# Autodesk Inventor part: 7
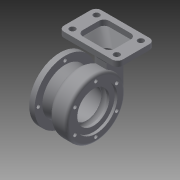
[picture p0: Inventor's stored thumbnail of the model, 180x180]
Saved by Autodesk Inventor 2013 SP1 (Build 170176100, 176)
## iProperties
Created: 2013-05
Part Number: 7
Material: Iron, Cast
Document SubType Name: Modeling
Designer: 50384
Density: 1 g/cm^3
Author: 50384
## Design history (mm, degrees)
sketch "Sketch1"
  geometry: L1 (0, 0)-(0, 40); L2 (0, 40)-(-5, 40); L3 (-5, 40)-(-5, 30); L4 (-5, 30)-(-10, 30); L5 (-10, 30)-(-10, 52); L6 (-10, 52)-(-22, 52); L7 (0, 40)-(0, 50); L8 (-5, 55)-(-22, 55); L9 (-37, 40)-(-37, 36.35); L10 (-57.45, 42.99)-(-37, 36.35); L11 (-57.45, 42.99)-(-57.45, 57.49); L12 (-57.45, 57.49)-(-67.45, 57.49); L13 (-67.45, 57.49)-(-67.45, 43.06); L14 (-17.435, 27.47)-(-63.445, 38.16); L15 (-17.435, 27.47)-(-18.622, 27.746); L16 (-17.895, 28.724)-(-34, 35.468); L17 (-34, 35.468)-(-34, 40); L18 (0, 0)-(-62.45, 0); A1 r 5 centre (-5, 50) between (0, 50) and (-5, 55); A2 r 5 centre (-62.45, 43.06) between (-67.45, 43.06) and (-63.445, 38.16); A3 r 1.219 centre (-18.622, 27.746) between (-17.435, 27.47) and (-17.895, 28.724); A4 r 12 centre (-22, 40) between (-22, 52) and (-34, 40); A5 r 15 centre (-22, 40) between (-22, 55) and (-37, 40); 1 further point
  constraints: 36 end point, 10 point on circle, 8 perpendicular, 5 centre point, 4 tangent, 3 parallel, 3 point on line, 2 coincident, 1 vertical
  dimensions: "d7" = 15 distance of L1.end point (0, 55); "d8" = 22 distance of point (0, 55) L8.end; "d9" = 5 radius of A1; "d12" = 3.65 distance of L9.start L9.end; "d15" = 14.5 distance of L10.start L11.end; "d16" = 10 distance of L11.end L12.end; "d17" = 14.43 distance of L13.end L12.end
revolve "Revolution1" sketch "Sketch1" stored, may be unused: angle "d22" = 90 deg
sketch "Sketch2" dims "d23" = 100
  geometry: C1 r 43.06 at (0, 0) reference; C2 r 3.4 at (0, 50); C3 r 3.4 at (-50, 0); C4 r 3.4 at (0, -50); C5 r 3.4 at (50, 0); 1 further point
  constraints: 4 centre point, 1 coincident, 1 vertical alignment, 11 other
  dimensions: "d24" = 6.8 diameter of C2; "d27" = 360 deg dimension on point (0, 0) C2.centre (derived)
extrude "Extrusion1" cut sketch "Sketch2" stored distance "d29" = 25.4; taper "d30" = 0 deg
workplane "Work Plane1"
sketch "Sketch3"
  geometry: L1 (5, 55)-(5, -55) reference; L2 (20, -75)-(75, -75); L3 (65, -75)-(-25, -75); L4 (-35, -65)-(-35, -15); L5 (-25, -5)-(65, -5); L6 (75, -15)-(75, -65); L7 (20, -5)-(20, -15); L8 (20, -15)-(0, -15); L9 (-35, -40)-(-10, -40); L10 (-10, -40)-(-10, -25); L11 (20, -65)-(0, -65); L12 (-10, -40)-(-10, -55); L13 (20, -15)-(40, -15); L14 (50, -40)-(50, -25); L15 (50, -40)-(50, -55); L16 (20, -65)-(40, -65); C1 r 5.5 at (61.46, -17.5); C2 r 5.5 at (61.46, -62.5); C3 r 5.5 at (-21.46, -17.5); C4 r 5.5 at (-21.46, -62.5); A1 r 10 centre (0, -25) between (0, -15) and (-10, -25); A2 r 10 centre (-25, -15) between (-25, -5) and (-35, -15); A3 r 10 centre (-25, -65) between (-35, -65) and (-25, -75); A4 r 10 centre (65, -65) between (65, -75) and (75, -65); A5 r 10 centre (65, -15) between (75, -15) and (65, -5); A6 r 10 centre (0, -55) between (-10, -55) and (0, -65); A7 r 10 centre (40, -25) between (50, -25) and (40, -15); A8 r 10 centre (40, -55) between (40, -65) and (50, -55); 4 further points
  constraints: 30 end point, 16 point on circle, 12 centre point, 11 symmetric about line, 10 tangent, 8 point on line, 4 equal radius, 4 parallel, 3 perpendicular, 2 midpoint, 1 horizontal, 3 other
  dimensions: "d35" = 55 distance of L2.start L2.end; "d36" = 110 distance of point (-35, -5) point (75, -5); "d37" = 70 distance of point (-35, -75) point (-35, -5); "d40" = 11 diameter of C1; "d41" = 10 distance of L7.start L7.end; "d42" = 25 distance of L9.start L9.end; "d43" = 10 radius of A1
extrude "Extrusion2" join sketch "Sketch3" distance "d44" = 10; taper "d45" = 0 deg
workplane "Work Plane2"
sketch "Sketch4"
  geometry: L1 (-10, -55)-(-10, -25) reference; L2 (0, -15)-(40, -15) reference; L3 (50, -25)-(50, -55) reference; L4 (40, -65)-(0, -65) reference; L5 (-35, -15)-(-35, -65) reference; L6 (-25, -75)-(65, -75) reference; L7 (75, -65)-(75, -15) reference; L8 (65, -5)-(-25, -5) reference; L9 (8, -40)-(8, -28); L10 (8, -28)-(20, -28); L11 (8, -52)-(20, -52); L12 (8, -40)-(8, -52); L13 (4, -28)-(4, -55); L14 (20, -24)-(4, -24); L15 (4, -24)-(4, -28); L16 (20, -56)-(4, -56); L17 (4, -56)-(4, -55); C1 r 5.5 at (-21.46, -62.5) reference; C2 r 5.5 at (61.46, -62.5) reference; C3 r 5.5 at (61.46, -17.5) reference; C4 r 5.5 at (-21.46, -17.5) reference; A1 r 10 centre (0, -25) between (0, -15) and (-10, -25) reference; A2 r 10 centre (40, -25) between (50, -25) and (40, -15) reference; A3 r 10 centre (40, -55) between (40, -65) and (50, -55) reference; A4 r 10 centre (0, -55) between (-10, -55) and (0, -65) reference; A5 r 10 centre (-25, -65) between (-35, -65) and (-25, -75) reference; A6 r 10 centre (65, -65) between (65, -75) and (75, -65) reference; A7 r 10 centre (65, -15) between (75, -15) and (65, -5) reference; A8 r 10 centre (-25, -15) between (-25, -5) and (-35, -15) reference; A9 r 12 centre (20, -40) between (20, -52) and (20, -28); A10 r 16 centre (20, -40) between (20, -56) and (20, -24)
  constraints: 18 end point, 4 point on circle, 2 centre point, 2 perpendicular, 2 tangent, 1 coincident, 1 collinear
  dimensions: "d52" = 4 distance of L11.end L16.start
  node "Projected Loop1"
sketch "Sketch5"
  geometry: L1 (10, -25)-(10, -55) reference; L2 (0, -65)-(-40, -65) reference; L3 (-50, -55)-(-50, -25) reference; L4 (-40, -15)-(0, -15) reference; L5 (0, -12.399)-(-40, -12.399); L6 (-52.601, -25)-(-52.601, -55); L7 (-40, -67.601)-(0, -67.601); L8 (12.601, -55)-(12.601, -25); A1 r 10 centre (0, -55) between (0, -65) and (10, -55) reference; A2 r 10 centre (-40, -55) between (-50, -55) and (-40, -65) reference; A3 r 10 centre (-40, -25) between (-40, -15) and (-50, -25) reference; A4 r 10 centre (0, -25) between (10, -25) and (0, -15) reference; A5 r 12.601 centre (-40, -25) between (-40, -12.399) and (-52.601, -25); A6 r 12.601 centre (-40, -55) between (-52.601, -55) and (-40, -67.601); A7 r 12.601 centre (0, -55) between (0, -67.601) and (12.601, -55); A8 r 12.601 centre (0, -25) between (12.601, -25) and (0, -12.399); 1 further point
  constraints: 8 end point, 8 point on circle, 4 centre point, 7 other
loft "Loft1" dims "d53" = 0, "d54" = 90 deg, "d55" = 0, "d56" = 90 deg
loft "Loft2" dims "d57" = 0, "d58" = 90 deg, "d59" = 0, "d60" = 90 deg
sketch "Sketch6"
  geometry: L1 (12, -4)-(12, -19.752) reference; L2 (12, -28)-(0, -28) reference; L3 (0, -4)-(8.616, -4) reference; L4 (16, 0)-(16, -9.102) reference; L5 (0, 0)-(16, 0) reference; L6 (16, -22.898)-(16, -32) reference; L7 (16, -9.102)-(16, -22.898) reference; L8 (-2, -31)-(15, -31) reference; L9 (-2, -31)-(-2, 79) reference; L10 (-17, -16)-(-17, 64) reference; L11 (16, -30.899)-(-8.75, -29.395); A1 r 16 centre (0, -16) between (0, 0) and (-12.469, -5.974) reference; A2 r 16 centre (0, -16) between (-12.469, -5.974) and (-12.469, -26.026) reference; A3 r 16 centre (0, -16) between (-12.469, -26.026) and (0, -32) reference; A4 r 5 centre (15, -26) between (15, -31) and (20, -26) reference; A5 r 15 centre (-2, -16) between (-17, -16) and (-2, -31) reference; 3 further points
  constraints: 3 point on circle, 2 end point, 2 vertical alignment, 1 horizontal alignment, 1 point on line, 2 other
extrude "Extrusion3" join sketch "Sketch6" stored distance "d61" = 127; taper "d62" = 0 deg
sketch "Sketch7"
  geometry: L1 (-20, 28)-(-8, 28) reference; L2 (-8, 28)-(-8, 52) reference; L3 (-8, 52)-(-20, 52) reference; L4 (-22, 51.832)-(-22, 28.168) reference; L5 (-22, 51.832)-(-22, 28.168) reference; L6 (-8.824, 28)-(-8.824, 52); L7 (-32, 40)-(-8, 40); L8 (-10.4, 28)-(-10.4, 52); L9 (-32, 40)-(-8, 40); L10 (-22, 40)-(-10.4, 40); L11 (-10.4, 40)-(-10.4, 52); L12 (-10.4, 52)-(-22, 52); L13 (-22, 52)-(-22, 40); L14 (-10.4, 40.546)-(-8.824, 40.546); L15 (-8.824, 40.546)-(-8.824, 52); L16 (-8.824, 52)-(-10.4, 52); L17 (-10.4, 52)-(-10.4, 40.546); L18 (-10.4, 40)-(-8, 40); L19 (-8, 40)-(-8, 52); L20 (-8, 52)-(-10.4, 52); L21 (-10.4, 52)-(-10.4, 40); L22 (-22, 40)-(-30.84, 34.853); 3 further points
  constraints: 34 end point, 6 parallel, 6 perpendicular, 6 point on line, 3 horizontal, 2 midpoint, 7 other
  node "Projected Loop3"
  node "Projected Loop4"
extrude "Extrusion4" cut sketch "Sketch7" distance "d63" = 63.5; taper "d64" = 0 deg
extrude "Extrusion5" cut sketch "Sketch7" distance "d65" = 88.9; taper "d66" = 0 deg
sketch "Sketch8" dims "d67" = 90
  geometry: C1 r 50 at (0, 0) reference; C2 r 3.4 at (0, 45); C3 r 3.4 at (-38.971, 22.5); C4 r 3.4 at (-38.971, -22.5); C5 r 3.4 at (0, -45); C6 r 3.4 at (38.971, -22.5); C7 r 3.4 at (38.971, 22.5); 1 further point
  constraints: 6 centre point, 1 coincident, 1 vertical alignment, 15 other
  dimensions: "d68" = 6.8 diameter of C2; "d71" = 360 deg dimension on point (0, 0) C2.centre (derived)
extrude "Extrusion6" cut sketch "Sketch8" stored distance "d73" = 88.9; taper "d74" = 0 deg
body "Solid1"
node "Projected Loop2"
